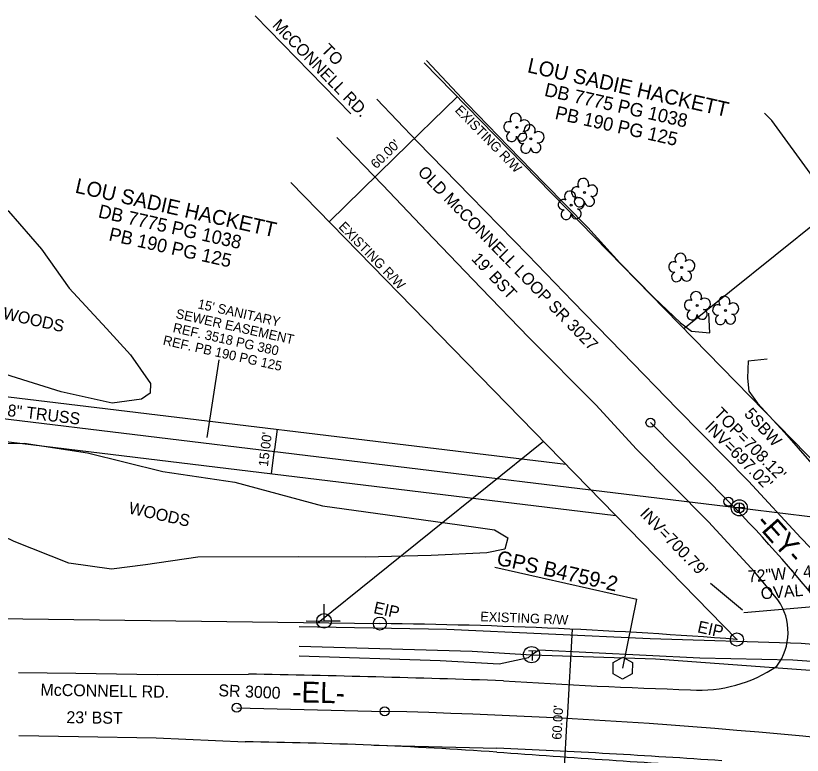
# Model space of a CAD drawing. Extents: x 1784037 to 1786391, y 840555 to 842045.
# Drawn here: x 1784833 to 1785096.6, y 841546.6 to 841794.3 of the extents above; entities that cross this region are included whole.
import ezdxf

# ---------------------------------------------------------------- set-up
doc = ezdxf.new("R2010")
doc.units = 0
for name, color, linetype in [('CTL GPS Vertical CELL', 7, 'Continuous'), ('Exist Horizontal Alignment', 7, 'Continuous'), ('Exist Horizontal Alignment Direction Label', 7, 'Continuous'), ('Exist Horizontal Alignment Station Label', 7, 'Continuous'), ('Exist Other Culture Fence Line', 7, 'Continuous'), ('Exist Other Culture Fence Line Text', 7, 'Continuous'), ('Exist Other Culture Gate', 7, 'Continuous'), ('Exist Property Deed Book Text', 7, 'Continuous'), ('Exist Property Iron Pin CELL', 7, 'Continuous'), ('Exist Property Iron Pin Text', 7, 'Continuous'), ('Exist Property Owner Text', 7, 'Continuous'), ('Exist Right of Way Easement Line', 7, 'Continuous'), ('Exist Right of Way Easement Line Text', 7, 'Continuous'), ('Exist Right of Way Line', 7, 'Continuous'), ('Exist Right of Way Line Text', 7, 'Continuous'), ('Exist Right of Way Width CELL', 7, 'Continuous'), ('Exist Roads EOP', 7, 'Continuous'), ('Exist Roads EOP Leader', 7, 'Continuous'), ('Exist Roads EOP Text', 7, 'Continuous'), ('Exist Roads EOT', 7, 'Continuous'), ('Exist Structure Minor Pipes CMP 72 Inch', 7, 'Continuous'), ('Exist Structure Minor Pipes CMP 72 Inch Invert', 7, 'Continuous'), ('Exist Structure Minor Pipes CMP 72 Inch Text', 7, 'Continuous'), ('Exist Utilities Power Joint Use Telephone CELL', 7, 'Continuous'), ('Exist Utilities Sanitary Sewer Manhole CELL', 7, 'Continuous'), ('Exist Utilities Sanitary Sewer Manhole Top Elevation', 7, 'Continuous'), ('Exist Utilities Sanitary Sewer UG Line', 7, 'Continuous'), ('Exist Utilities Sanitary Sewer UG Line Invert Elevation', 7, 'Continuous'), ('Exist Utilities Sanitary Sewer UG Line Text', 7, 'Continuous'), ('Exist Utilities Telephone Manhole CELL', 7, 'Continuous'), ('Exist Utilities Telephone UG Cable SUE LOS B', 7, 'Continuous'), ('Exist Utilities Telephone UG Conduit SUE LOS B', 7, 'Continuous'), ('Exist Utilities Water Test Hole SUE LOS A CELL', 7, 'Continuous'), ('Exist Vegetation Tree CELL', 7, 'Continuous'), ('Exist Vegetation Woods Line', 7, 'Continuous'), ('Exist Vegetation Woods Line Text', 7, 'Continuous')]:
    doc.layers.add(name, color=color, linetype=linetype)

msp = doc.modelspace()

# ---------------------------------------------------------------- linework, layer by layer
at = {"layer": 'CTL GPS Vertical CELL'}
msp.add_line((1785036.41, 841575.72), (1785036.41, 841575.72), dxfattribs=at)
msp.add_lwpolyline([(1785033.18, 841577.59), (1785036.43, 841579.41), (1785039.68, 841577.62), (1785039.63, 841573.89), (1785036.38, 841572.01), (1785033.18, 841573.82)], close=True, dxfattribs=at)
at = {"layer": 'Exist Horizontal Alignment'}
for p, q in [((1785071.85, 841631.56), (1785045.72, 841658.01)), ((1784907.07, 841562.47), (1784956.68, 841561.26))]:
    msp.add_line(p, q, dxfattribs=at)
for centre, radius, start, end in [((1784751.76, 841315.27), 450, 31.2576, 44.6575), ((1784908.02, 839561.86), 2000, 75.06834, 88.60574)]:
    msp.add_arc(centre, radius, start, end, dxfattribs=at)
at = {"layer": 'Exist Horizontal Alignment Station Label'}
for centre in [(1785045.72, 841658.01), (1785071.85, 841631.56), (1784907.07, 841562.47), (1784956.68, 841561.26)]:
    msp.add_circle(centre, 1.5, dxfattribs=at)
at = {"layer": 'Exist Other Culture Fence Line'}
for points in [[(1784970.69, 841779.36), (1784984.29, 841764.8), (1784998.19, 841750.53), (1785010.15, 841738.24), (1785024.73, 841723.36), (1785035.47, 841711.52), (1785046.85, 841699.94), (1785055.74, 841691.5), (1785059.49, 841688.63), (1785065.66, 841688.07)], [(1785078.47, 841678.66), (1785078.25, 841672.9), (1785078.68, 841668.5), (1785081.56, 841664.5), (1785090.62, 841654.67), (1785099.76, 841644.18), (1785111.08, 841633.31), (1785122.74, 841621.83), (1785129.59, 841616.14), (1785137.59, 841610.77), (1785145.61, 841607.68), (1785162.57, 841602.22), (1785196.67, 841595.15), (1785230.52, 841587.15), (1785263.45, 841585.88), (1785296.82, 841585.7), (1785326.71, 841585.28), (1785336.8, 841586.13), (1785342.54, 841586.56)]]:
    msp.add_lwpolyline(points, dxfattribs=at)
at = {"layer": 'Exist Other Culture Gate'}
for points in [[(1785065.66, 841688.07), (1785065.24, 841694.71)], [(1785078.47, 841678.66), (1785084.82, 841679.41)]]:
    msp.add_lwpolyline(points, dxfattribs=at)
at = {"layer": 'Exist Property Iron Pin CELL'}
for centre, radius in [((1784955.06, 841590.68), 2.2), ((1784955.06, 841590.68), 0.0707), ((1785074.69, 841585.34), 2.2), ((1785074.69, 841585.34), 0.0707)]:
    msp.add_circle(centre, radius, dxfattribs=at)
at = {"layer": 'Exist Property Owner Text'}
msp.add_line((1784897.2, 841652.99), (1784901.15, 841679), dxfattribs=at)
at = {"layer": 'Exist Right of Way Easement Line'}
for p, q in [((1784790.21, 841671.59), (1785017.35, 841644.05)), ((1784788.41, 841656.7), (1785034.09, 841626.91))]:
    msp.add_line(p, q, dxfattribs=at)
at = {"layer": 'Exist Right of Way Easement Line Text'}
for p in [(1784920.59, 841655.78), (1784918.78, 841640.89)]:
    msp.add_line(p, (1784919.77, 841649.03), dxfattribs=at)
at = {"layer": 'Exist Right of Way Line'}
for p, q in [((1785167.95, 841575.74), (1784969.85, 841778.57)), ((1785157.97, 841770.67), (1785056.9, 841689.44)), ((1785074.69, 841585.34), (1784925.2, 841738.41)), ((1785009.91, 841651.68), (1784934.34, 841590.95)), ((1784808.58, 841592.57), (1784955.06, 841590.68))]:
    msp.add_line(p, q, dxfattribs=at)
msp.add_arc((1784934.08, 839777.99), 1812.82, 85.55126, 89.33687, dxfattribs=at)
at = {"layer": 'Exist Right of Way Width CELL'}
for p, q in [((1784980.96, 841767.19), (1784960.1, 841746.81)), ((1784938.04, 841725.26), (1784960.1, 841746.81)), ((1785019.44, 841588.8), (1785017.79, 841558.83)), ((1785016.14, 841528.89), (1785017.79, 841558.83))]:
    msp.add_line(p, q, dxfattribs=at)
at = {"layer": 'Exist Roads EOP'}
msp.add_line((1785088.41, 841598.6), (1785080.64, 841607.91), dxfattribs=at)
for points in [[(1784954.03, 841766.33), (1784967.67, 841752.11), (1784985.45, 841733.87), (1785004.58, 841714.23), (1785019.7, 841698.59), (1785036.11, 841681.76), (1785054.75, 841662.5)], [(1785004.92, 841686.56), (1784988.96, 841703.04), (1784973, 841719.71), (1784955.88, 841737.67), (1784940.67, 841753.52)], [(1785041.09, 841649.07), (1785027.4, 841663.93), (1785004.92, 841686.56)], [(1785054.75, 841662.5), (1785078.52, 841638.35), (1785096.14, 841619.4), (1785117.45, 841597.32)], [(1785080.64, 841607.91), (1785065.19, 841624.77), (1785041.09, 841649.07)], [(1784833.94, 841574.27), (1784853.14, 841574.04), (1784880.46, 841573.63), (1784910.98, 841573.74)], [(1784834.02, 841553.2), (1784854.1, 841552.86), (1784880.04, 841552.35), (1784909.93, 841551.03)]]:
    msp.add_lwpolyline(points, dxfattribs=at)
for centre, major_axis, ratio, start_param, end_param in [((1785072.9, 841587.72), (8.59, 16.9), 0.998809, 4.544918, 5.793555), ((1785062.28, 841613.9), (38.46, 24.32), 0.999812, 4.080453, 4.752096), ((1784805.28, 836091.36), (-5589.05, -36.42), 0.981063, 4.671784, 4.687083), ((1785111.18, 843301.81), (613.02, -1622.11), 0.999956, 5.855641, 5.891859), ((1784892.58, 840077.13), (-1469.69, 136.09), 0.998657, 4.735643, 4.792845), ((1785273.77, 845367.26), (4154.31, -331.76), 0.918971, 4.7185, 4.736578)]:
    msp.add_ellipse(centre, major_axis=major_axis, ratio=ratio, start_param=start_param, end_param=end_param, dxfattribs=at)
at = {"layer": 'Exist Roads EOP Leader'}
msp.add_line((1784913.21, 841794.34), (1784945.36, 841761.44), dxfattribs=at)
at = {"layer": 'Exist Roads EOT'}
msp.add_line((1784953.05, 841549.89), (1784994.25, 841548.97), dxfattribs=at)
msp.add_ellipse((1784845.01, 838284.83), major_axis=(-3298.97, 29.38), ratio=0.990423, start_param=4.653056, end_param=4.675957, dxfattribs=at)
at = {"layer": 'Exist Structure Minor Pipes CMP 72 Inch'}
msp.add_line((1785076.99, 841594.42), (1785134.37, 841599.28), dxfattribs=at)
at = {"layer": 'Exist Structure Minor Pipes CMP 72 Inch Invert'}
msp.add_line((1785076.59, 841595.19), (1785065.8, 841604.15), dxfattribs=at)
at = {"layer": 'Exist Utilities Power Joint Use Telephone CELL'}
msp.add_line((1784936.34, 841591.56), (1784936.34, 841591.56), dxfattribs=at)
msp.add_lwpolyline([(1784930.4, 841591.56), (1784941.74, 841591.53), (1784936.34, 841591.54), (1784936.34, 841597.19)], dxfattribs=at)
msp.add_circle((1784936.34, 841591.57), 2.45, dxfattribs=at)
at = {"layer": 'Exist Utilities Sanitary Sewer Manhole CELL'}
msp.add_lwpolyline([(1785075.48, 841631.16), (1785075.48, 841627.74), (1785075.48, 841629.45), (1785077.2, 841629.45), (1785073.77, 841629.45)], dxfattribs=at)
for radius in [2.69, 1.71]:
    msp.add_circle((1785075.48, 841629.45), radius, dxfattribs=at)
at = {"layer": 'Exist Utilities Sanitary Sewer UG Line'}
for p, q in [((1784789.31, 841664.14), (1785075.48, 841629.45)), ((1785075.48, 841629.45), (1785470.01, 841580.57))]:
    msp.add_line(p, q, dxfattribs=at)
at = {"layer": 'Exist Utilities Telephone Manhole CELL'}
msp.add_circle((1785005.87, 841580.27), 2.72, dxfattribs=at)
at = {"layer": 'Exist Utilities Telephone UG Cable SUE LOS B'}
msp.add_lwpolyline([(1784927.98, 841579.83), (1784975.2, 841578.26), (1784995, 841577.21), (1785004.8, 841579.3), (1785005.87, 841580.26)], dxfattribs=at)
at = {"layer": 'Exist Utilities Telephone UG Conduit SUE LOS B'}
for points in [[(1784928.05, 841589.68), (1784977.44, 841588.79), (1785045.59, 841585.65), (1785096.16, 841584.08), (1785147.53, 841579.79), (1785223.95, 841569.41), (1785281.27, 841561.43), (1785341.54, 841551.4), (1785414.22, 841535.89), (1785463.58, 841519.55), (1785545.63, 841491.96), (1785568.22, 841485.69), (1785622.97, 841470.63), (1785677.94, 841455.48), (1785722.13, 841445.28), (1785786.53, 841428.1), (1785793.16, 841426.49), (1785850.79, 841412.3)], [(1784928, 841583.07), (1784986.03, 841581.43), (1785005.87, 841580.26)], [(1785005.87, 841580.26), (1785008.36, 841581.93), (1785062.26, 841579.21), (1785093.39, 841578.51), (1785144.97, 841574.87), (1785185.01, 841564.27), (1785220.42, 841557.21), (1785276.71, 841548.86), (1785332.97, 841538.64), (1785392.81, 841526.16), (1785444.96, 841509.52), (1785469.05, 841500.37), (1785627.28, 841457.29), (1785668.69, 841450.12), (1785707.44, 841442.24), (1785711.37, 841439.59)], [(1785005.87, 841580.26), (1785047.36, 841578.88), (1785094.69, 841575.39), (1785155.58, 841571.08), (1785221.47, 841554.76), (1785277.4, 841546.34), (1785356.59, 841532.89), (1785417.24, 841517.03), (1785459.64, 841501.34), (1785469.4, 841498.6), (1785627.24, 841456.89), (1785662.63, 841448.15), (1785707.93, 841440.35), (1785711.37, 841439.59)]]:
    msp.add_lwpolyline(points, dxfattribs=at)
at = {"layer": 'Exist Utilities Water Test Hole SUE LOS A CELL'}
for p in [(1784993.52, 841609.55), (1785036.41, 841575.72)]:
    msp.add_line(p, (1785041.14, 841598.87), dxfattribs=at)
at = {"layer": 'Exist Vegetation Tree CELL'}
for p, q in [((1785000.9, 841756.95), (1785000.9, 841756.95)), ((1785005.62, 841753.06), (1785005.62, 841753.06)), ((1785023.58, 841735.1), (1785023.58, 841735.1)), ((1785019.15, 841730.88), (1785019.15, 841730.88)), ((1785056.17, 841710.02), (1785056.17, 841710.02)), ((1785061.39, 841697.22), (1785061.39, 841697.22)), ((1785070.87, 841695.62), (1785070.87, 841695.62))]:
    msp.add_line(p, q, dxfattribs=at)
for centre in [(1785000.9, 841756.95), (1785005.62, 841753.06), (1785023.58, 841735.1), (1785019.15, 841730.88), (1785056.17, 841710.02), (1785061.39, 841697.22), (1785070.87, 841695.62)]:
    msp.add_circle(centre, 0.326, dxfattribs=at)
for centre, radius, start, end in [((1785000.52, 841759.82), 1.86, 330.1651, 219.7134), ((1784998.3, 841757.1), 1.73, 62.6636, 279.3457), ((1785003.45, 841757.54), 1.9, 257.1011, 134.1999), ((1785005.24, 841755.94), 1.86, 330.1651, 219.7134), ((1784999.2, 841753.83), 1.69, 111.5671, 6.231), ((1785002.57, 841754.05), 1.7, 181.2822, 74.56), ((1785003.02, 841753.22), 1.73, 62.6636, 279.3457), ((1785008.17, 841753.65), 1.9, 257.1011, 134.1999), ((1785003.92, 841749.94), 1.69, 111.5671, 6.231), ((1785007.29, 841750.17), 1.7, 181.2822, 74.56), ((1785023.19, 841737.98), 1.86, 330.1651, 219.7134), ((1785020.97, 841735.26), 1.73, 62.6636, 279.3457), ((1785026.13, 841735.69), 1.9, 257.1011, 134.1999), ((1785018.76, 841733.75), 1.86, 330.1651, 219.7134), ((1785021.88, 841731.98), 1.69, 111.5671, 6.231), ((1785025.25, 841732.21), 1.7, 181.2822, 74.56), ((1785016.54, 841731.03), 1.73, 62.6636, 279.3457), ((1785021.7, 841731.47), 1.9, 257.1011, 134.1999), ((1785017.44, 841727.76), 1.69, 111.5671, 6.231), ((1785020.82, 841727.98), 1.7, 181.2822, 74.56), ((1785055.79, 841712.89), 1.86, 330.1651, 219.7134), ((1785058.72, 841710.61), 1.9, 257.1011, 134.1999), ((1785053.57, 841710.17), 1.73, 62.6636, 279.3457), ((1785054.47, 841706.9), 1.69, 111.5671, 6.231), ((1785057.84, 841707.12), 1.7, 181.2822, 74.56), ((1785061, 841700.09), 1.86, 330.1651, 219.7134), ((1785063.94, 841697.81), 1.9, 257.1011, 134.1999), ((1785070.49, 841698.49), 1.86, 330.1651, 219.7134), ((1785058.78, 841697.37), 1.73, 62.6636, 279.3457), ((1785068.27, 841695.77), 1.73, 62.6636, 279.3457), ((1785073.42, 841696.21), 1.9, 257.1011, 134.1999), ((1785059.68, 841694.1), 1.69, 111.5671, 6.231), ((1785063.06, 841694.32), 1.7, 181.2822, 74.56), ((1785069.17, 841692.5), 1.69, 111.5671, 6.231), ((1785072.54, 841692.72), 1.7, 181.2822, 74.56)]:
    msp.add_arc(centre, radius, start, end, dxfattribs=at)
at = {"layer": 'Exist Vegetation Woods Line'}
for points in [[(1785151.57, 841788.63), (1785150.34, 841787.89), (1785138.96, 841780.43), (1785128.16, 841773.25), (1785122.36, 841762.89), (1785119.1, 841751.12), (1785115, 841740.73), (1785111.96, 841735.87), (1785105.29, 841734.26), (1785100.07, 841740.31), (1785086.37, 841759.21), (1785083.89, 841761.66)], [(1784817.22, 841739.58), (1784818.52, 841738.94), (1784830.64, 841728.87), (1784841.64, 841716.11), (1784850.89, 841703.08), (1784863.44, 841689.55), (1784871.46, 841680.71), (1784878.16, 841671.14), (1784878.05, 841667.86), (1784875.16, 841665.9), (1784865.32, 841664.58), (1784848.27, 841668.38), (1784831.46, 841673.52), (1784815.45, 841679.04), (1784805.94, 841679.54), (1784792.76, 841680.64), (1784792.63, 841680.67)], [(1784790.21, 841654.8), (1784797.31, 841652.45), (1784811.62, 841650.89), (1784835.84, 841651.11), (1784857.04, 841647.89), (1784882.3, 841641.65), (1784906.48, 841638.04), (1784935.77, 841630.12), (1784957.56, 841627.11), (1784981.7, 841623.79), (1784993.45, 841622.06), (1784997.97, 841619.39), (1784996.92, 841615.61), (1784990.9, 841614.43), (1784972.19, 841613.44), (1784950.12, 841612.96), (1784927.85, 841613.06), (1784894, 841612.98), (1784876.57, 841610.37), (1784865.15, 841608.86), (1784850.86, 841610.88), (1784832.47, 841618.22), (1784822.25, 841623.11)]]:
    msp.add_lwpolyline(points, dxfattribs=at)

# ---------------------------------------------------------------- texts
at = {"layer": 'Exist Horizontal Alignment Direction Label'}
for s, rotation, p in [('-EY-', 311.5613, (1785080.54, 841624.19)), ('-EL-', 358.6057, (1784925.59, 841564.34))]:
    msp.add_text(s, height=7, rotation=rotation, dxfattribs=at).set_placement(p)
at = {"layer": 'Exist Other Culture Fence Line Text'}
msp.add_text('5SBW', height=4, rotation=312.6696, dxfattribs=at).set_placement((1785076.87, 841660.74))
at = {"layer": 'Exist Property Deed Book Text'}
for s, p in [('DB 7775 PG 1038', (1785009.93, 841767.53)), ('PB 190 PG 125', (1785013.46, 841759.82)), ('DB 7775 PG 1038', (1784860.42, 841726.82)), ('PB 190 PG 125', (1784863.96, 841719.11))]:
    msp.add_text(s, height=4.5, rotation=347.3599, dxfattribs=at).set_placement(p)
at = {"layer": 'Exist Property Iron Pin Text'}
for p in [(1784952.69, 841594.23), (1785061.22, 841587.8)]:
    msp.add_text('EIP', height=4, rotation=347.3599, dxfattribs=at).set_placement(p)
at = {"layer": 'Exist Property Owner Text'}
for p in [(1785004.21, 841775.43), (1784852.67, 841735.11)]:
    msp.add_text('LOU SADIE HACKETT', height=5, rotation=347.3599, dxfattribs=at).set_placement(p)
at = {"layer": 'Exist Right of Way Easement Line Text'}
for s, rotation, p in [("15' SANITARY", 347.3599, (1784893.8, 841696.33)), ('SEWER EASEMENT', 347.3599, (1784886.43, 841693.07)), ('REF. 3518 PG 380', 347.3599, (1784885.48, 841688.36)), ('REF. PB 190 PG 125', 347.3599, (1784882.17, 841684.18)), ("15.00'", 83.0881, (1784917.52, 841643.14))]:
    msp.add_text(s, height=3.2, rotation=rotation, dxfattribs=at).set_placement(p)
at = {"layer": 'Exist Right of Way Line Text'}
for rotation, p in [(314.3236, (1784979.99, 841762.47)), (314.3236, (1784941.01, 841723.43)), (357.7243, (1784988.65, 841591.49))]:
    msp.add_text('EXISTING R/W', height=3.2, rotation=rotation, dxfattribs=at).set_placement(p)
at = {"layer": 'Exist Right of Way Width CELL'}
for rotation, p in [(44.3236, (1784953.86, 841742.85)), (86.8537, (1785015.87, 841551.7))]:
    msp.add_text("60.00'", height=3.2, rotation=rotation, dxfattribs=at).set_placement(p)
at = {"layer": 'Exist Roads EOP Text'}
for s, rotation, p in [('McCONNELL RD.', 314.2527, (1784918.73, 841790.88)), ('TO', 314.2527, (1784935.12, 841782.64)), ('OLD McCONNELL LOOP SR 3027', 314.1748, (1784967.47, 841741.69)), ("19' BST", 313.3307, (1784985.48, 841712.69)), ('McCONNELL RD.', 359.022, (1784841.3, 841566.54)), ('SR 3000', 357.4726, (1784900.87, 841566.36)), ("23' BST", 359.1879, (1784849.99, 841557.33))]:
    msp.add_text(s, height=4, rotation=rotation, dxfattribs=at).set_placement(p)
at = {"layer": 'Exist Structure Minor Pipes CMP 72 Inch Invert'}
msp.add_text("INV=700.79'", height=4, rotation=314.2393, dxfattribs=at).set_placement((1785041.91, 841627.18))
at = {"layer": 'Exist Structure Minor Pipes CMP 72 Inch Text'}
for s, p in [('72"W x 42"H', (1785078.54, 841604.45)), ('OVAL CMP', (1785082.84, 841598.76))]:
    msp.add_text(s, height=4, rotation=4.844, dxfattribs=at).set_placement(p)
at = {"layer": 'Exist Utilities Sanitary Sewer Manhole Top Elevation'}
msp.add_text("TOP=708.12'", height=4, rotation=314.4507, dxfattribs=at).set_placement((1785066.7, 841660.77))
at = {"layer": 'Exist Utilities Sanitary Sewer UG Line Invert Elevation'}
msp.add_text("INV=697.02'", height=4, rotation=314.4507, dxfattribs=at).set_placement((1785063.69, 841656.26))
at = {"layer": 'Exist Utilities Sanitary Sewer UG Line Text'}
msp.add_text('8" TRUSS', height=4, rotation=353.0881, dxfattribs=at).set_placement((1784830.07, 841660.24))
at = {"layer": 'Exist Utilities Telephone Manhole CELL'}
msp.add_text('T', height=3.5, dxfattribs=at).set_placement((1785004.7, 841578.26))
at = {"layer": 'Exist Utilities Water Test Hole SUE LOS A CELL'}
msp.add_text('GPS B4759-2', height=5, rotation=347.3599, dxfattribs=at).set_placement((1784993.89, 841610.42))
at = {"layer": 'Exist Vegetation Woods Line Text'}
for p in [(1784828.45, 841692.84), (1784870.6, 841627.63)]:
    msp.add_text('WOODS', height=4, rotation=347.3599, dxfattribs=at).set_placement(p)

doc.saveas('drawing.dxf')
